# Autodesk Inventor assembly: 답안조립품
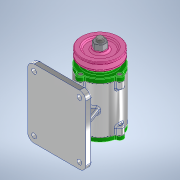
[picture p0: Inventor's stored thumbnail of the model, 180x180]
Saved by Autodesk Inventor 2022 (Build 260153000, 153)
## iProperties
Created: 2023-05
Part Number: 답안조립품
Document SubType Name: Assembly
Designer: Admin
Author: Admin
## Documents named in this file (12)
- C:\Users\Admin\Desktop\730508V1001\답안조립품.iam
- C:\Users\Admin\Desktop\730508V1001\본체.ipt
- C:\Users\Admin\Desktop\730508V1001\개스킷.ipt
- C:\Users\Admin\Desktop\730508V1001\앞커버.ipt
- C:\Users\Admin\Desktop\730508V1001\뒤커버.ipt
- C:\Users\Admin\Desktop\730508V1001\베어링 6204.ipt
- C:\Users\Admin\Desktop\730508V1001\축.ipt
- C:\Users\Admin\Desktop\730508V1001\오일 실.ipt
- C:\Users\Admin\Desktop\730508V1001\볼트 M4 x 12.ipt
- C:\Users\Admin\Desktop\730508V1001\키 4 x 4.ipt
- C:\Users\Admin\Desktop\730508V1001\V-벨트풀리.ipt
- C:\Users\Admin\Desktop\730508V1001\너트 M12 x 1.25.ipt
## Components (8 placed, 6 different names)
1. 개스킷:1
2. 개스킷:2
3. KS B 2023 6204 - 20 x 47 x 14:1
4. KS B 2023 6204 - 20 x 47 x 14:2
5. KS B 2804 D D - 20 32 8:1
6. KS B 1311 (I) 4 x 4 x 12:1
7. V-벨트풀리:2
8. KS B 1012 클래스 1 일반 - 미터 M12x1.25:2
